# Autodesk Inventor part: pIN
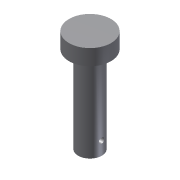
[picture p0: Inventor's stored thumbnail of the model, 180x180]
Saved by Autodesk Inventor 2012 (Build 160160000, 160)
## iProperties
Created: 2012-02
Part Number: pIN
Material: Default
Document SubType Name: Modeling
Designer: cadcim
Density: 1 g/cm^3
Author: cadcim
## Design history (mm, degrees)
sketch "Sketch1"
  geometry: C1 r 4 at (0, 0); 1 further point
  constraints: 1 centre point, 1 coincident
  dimensions: "d0" = 8 diameter of C1
extrude "Extrusion1" new body sketch "Sketch1" distance "d1" = 3; taper "d2" = 0 deg
sketch "Sketch2"
  geometry: C1 r 2.25 at (0, 0); 1 further point
  constraints: 1 centre point, 1 coincident
  dimensions: "d3" = 4.5 diameter of C1
extrude "Extrusion2" join sketch "Sketch2" distance "d4" = 16.5; taper "d5" = 0 deg
sketch "Sketch3"
  geometry: L1 (2.25, -16.5)-(-2.25, -16.5) reference; C1 r 0.5 at (0, -14); 1 further point
  constraints: 1 centre point
  dimensions: "d6" = 1 diameter of C1; "d9" = 2.5 distance from line of L1 C1.centre
extrude "Extrusion3" cut sketch "Sketch3" stored distance "d7" = 15; taper "d8" = 0 deg
body "Solid1"
